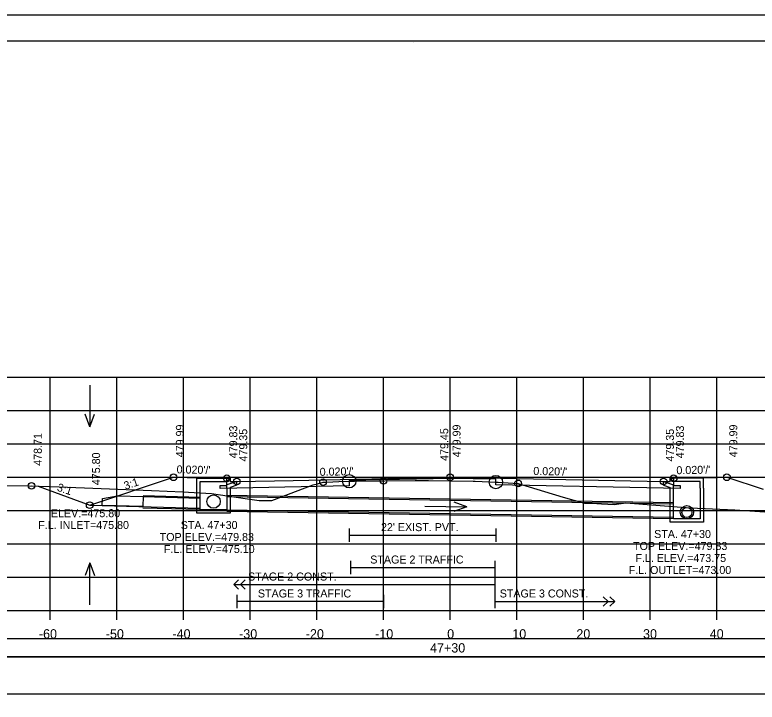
# Model space of a CAD drawing. Extents: x 1371057 to 1372761, y 380005 to 390517.
# Drawn here: x 1371495.6 to 1371606.9, y 382675.4 to 382778.5 of the extents above; entities that cross this region are included whole.
import ezdxf

# ---------------------------------------------------------------- set-up
doc = ezdxf.new("R2010")
doc.units = 0
for name, color, linetype in [('R_Alt Surface', 7, 'Continuous'), ('R_Axis', 7, 'Continuous'), ('R_Axis Annot', 7, 'Continuous'), ('R_Border', 7, 'Continuous'), ('R_Detour', 7, 'Continuous'), ('R_Dimension', 7, 'Continuous'), ('R_Exist Surface', 7, 'Continuous'), ('R_Fin Surface', 7, 'Continuous'), ('R_Grid', 7, 'Continuous'), ('R_No Plot', 7, 'Continuous'), ('R_Striping', 7, 'Continuous'), ('R_Water', 7, 'Continuous'), ('R_Water Annot', 7, 'Continuous'), ('R_Xsect Elev', 7, 'Continuous'), ('R_Xsect Slope', 7, 'Continuous')]:
    doc.layers.add(name, color=color, linetype=linetype)

msp = doc.modelspace()

# ---------------------------------------------------------------- linework, layer by layer
at = {"layer": 'R_Alt Surface'}
for points in [[(1371594.37, 382708.95), (1371594.37, 382707.87), (1371595.37, 382707.85), (1371595.37, 382707.42), (1371592.87, 382707.47), (1371567.72, 382707.97), (1371567.72, 382708.8), (1371560.87, 382708.94), (1371545.72, 382708.63), (1371545.72, 382707.8), (1371528.87, 382707.47), (1371526.37, 382707.42), (1371526.37, 382707.85), (1371527.37, 382707.87), (1371527.37, 382708.95)], [(1371594.37, 382708.95), (1371594.37, 382707.87), (1371595.37, 382707.85), (1371595.37, 382707.42), (1371592.87, 382707.47), (1371567.72, 382707.97), (1371567.72, 382708.8), (1371560.87, 382708.94), (1371545.72, 382708.63), (1371545.72, 382707.8), (1371528.87, 382707.47), (1371526.37, 382707.42), (1371526.37, 382707.85), (1371527.37, 382707.87), (1371527.37, 382708.95)], [(1371545.72, 382701.43), (1371545.72, 382699.43)], [(1371567.72, 382701.43), (1371567.72, 382699.43)], [(1371545.72, 382700.43), (1371567.72, 382700.43)]]:
    msp.add_lwpolyline(points, dxfattribs=at)
at = {"layer": 'R_Axis'}
for p, q in [((1371410.87, 382689.12), (1371710.87, 382689.12)), ((1371500.87, 382687.72), (1371500.87, 382689.12)), ((1371510.87, 382687.72), (1371510.87, 382689.12)), ((1371520.87, 382687.72), (1371520.87, 382689.12)), ((1371530.87, 382687.72), (1371530.87, 382689.12)), ((1371540.87, 382687.72), (1371540.87, 382689.12)), ((1371550.87, 382687.72), (1371550.87, 382689.12)), ((1371560.87, 382687.72), (1371560.87, 382689.12)), ((1371570.87, 382687.72), (1371570.87, 382689.12)), ((1371580.87, 382687.72), (1371580.87, 382689.12)), ((1371590.87, 382687.72), (1371590.87, 382689.12)), ((1371600.87, 382687.72), (1371600.87, 382689.12))]:
    msp.add_line(p, q, dxfattribs=at)
at = {"layer": 'R_Border'}
for p, q in [((1371402.87, 382774.58), (1371719.05, 382774.58)), ((1371555.39, 382774.32), (1371555.39, 382774.32)), ((1371555.39, 382774.32), (1371555.39, 382774.32))]:
    msp.add_line(p, q, dxfattribs=at)
at = {"layer": 'R_Detour'}
msp.add_lwpolyline([(1371407.72, 382682.16), (1371714.03, 382682.16), (1371714.03, 382684.87), (1371407.72, 382684.87)], close=True, dxfattribs=at)
at = {"layer": 'R_Dimension'}
msp.add_lwpolyline([(1371407.72, 382676.64), (1371714.03, 382676.64), (1371714.03, 382682.16), (1371407.72, 382682.16)], close=True, dxfattribs=at)
at = {"layer": 'R_Exist Surface'}
msp.add_lwpolyline([(1371492.96, 382707.86), (1371497.74, 382707.84), (1371502.2, 382707.69), (1371516.07, 382707.12), (1371520.75, 382706.94), (1371525.06, 382706.67), (1371530.11, 382705.9), (1371532.23, 382705.64), (1371533.39, 382705.63), (1371534.1, 382705.61), (1371539.13, 382707.52), (1371540.33, 382707.96), (1371540.98, 382708.13), (1371541.79, 382708.37), (1371542.34, 382708.39), (1371544.15, 382708.46), (1371545.72, 382708.52), (1371546.06, 382708.52), (1371546.51, 382708.53), (1371555.6, 382708.63), (1371556.12, 382708.63), (1371556.33, 382708.63), (1371556.87, 382708.62), (1371556.91, 382708.62), (1371556.91, 382708.62), (1371557.63, 382708.61), (1371564.29, 382708.51), (1371564.61, 382708.5), (1371567.72, 382708.38), (1371568.05, 382708.36), (1371571.04, 382708.19), (1371577.82, 382706.12), (1371581.01, 382705.24), (1371582.84, 382705.15), (1371583.56, 382705.1), (1371585.45, 382705.04), (1371587.2, 382705.26), (1371596.85, 382704.53), (1371603.55, 382704.22), (1371613.29, 382703.57)], dxfattribs=at)
at = {"layer": 'R_Fin Surface'}
msp.add_lwpolyline([(1371498.06, 382707.83), (1371499.08, 382707.79), (1371506.79, 382704.92), (1371506.79, 382704.92), (1371506.79, 382704.92), (1371519.37, 382709.11), (1371519.37, 382709.11), (1371519.37, 382709.11), (1371523.44, 382709.03), (1371524.37, 382709.01), (1371524.65, 382709), (1371527.37, 382708.95), (1371527.66, 382708.95), (1371527.87, 382708.95), (1371527.88, 382708.45), (1371528.87, 382708.47), (1371537.29, 382708.64), (1371560.87, 382709.11), (1371560.88, 382709.11), (1371570.93, 382708.91), (1371592.87, 382708.47), (1371593.71, 382708.45), (1371593.87, 382708.45), (1371593.87, 382708.68), (1371593.87, 382708.95), (1371593.95, 382708.95), (1371594.37, 382708.95), (1371597.37, 382709.01), (1371600.93, 382709.08), (1371602.37, 382709.11), (1371607.78, 382707.3)], dxfattribs=at)
at = {"layer": 'R_Grid'}
for p, q in [((1371410.87, 382724.12), (1371710.87, 382724.12)), ((1371500.87, 382689.12), (1371500.87, 382724.12)), ((1371510.87, 382689.12), (1371510.87, 382724.12)), ((1371520.87, 382689.12), (1371520.87, 382724.12)), ((1371530.87, 382689.12), (1371530.87, 382724.12)), ((1371540.87, 382689.12), (1371540.87, 382724.12)), ((1371550.87, 382689.12), (1371550.87, 382724.12)), ((1371560.87, 382689.12), (1371560.87, 382724.12)), ((1371570.87, 382689.12), (1371570.87, 382724.12)), ((1371580.87, 382689.12), (1371580.87, 382724.12)), ((1371590.87, 382689.12), (1371590.87, 382724.12)), ((1371600.87, 382689.12), (1371600.87, 382724.12)), ((1371410.87, 382719.12), (1371710.87, 382719.12)), ((1371410.87, 382714.12), (1371710.87, 382714.12)), ((1371410.87, 382709.12), (1371710.87, 382709.12)), ((1371410.87, 382704.12), (1371710.87, 382704.12)), ((1371410.87, 382699.12), (1371710.87, 382699.12)), ((1371410.87, 382694.12), (1371710.87, 382694.12)), ((1371410.87, 382689.12), (1371710.87, 382689.12))]:
    msp.add_line(p, q, dxfattribs=at)
at = {"layer": 'R_No Plot'}
for p, q in [((1371390.47, 382778.47), (1371723.8, 382778.47)), ((1371514.79, 382706.36), (1371523.37, 382706.13)), ((1371527.37, 382706.42), (1371594.37, 382705.32)), ((1371514.74, 382704.53), (1371523.37, 382704.3)), ((1371527.37, 382704.01), (1371594.37, 382702.9))]:
    msp.add_line(p, q, dxfattribs=at)
for points in [[(1371390.46, 382778.47), (1371723.8, 382778.47), (1371723.8, 382565.13), (1371390.46, 382565.13)], [(1371636.79, 382774.58), (1371656.41, 382774.58), (1371656.41, 382764.7), (1371672.52, 382764.7), (1371695.72, 382764.7), (1371695.84, 382736.54), (1371719.05, 382736.54), (1371719.05, 382569.12), (1371402.87, 382569.12), (1371402.87, 382774.58)]]:
    msp.add_lwpolyline(points, close=True, dxfattribs=at)
for centre, radius in [((1371519.37, 382709.11), 0.5), ((1371527.37, 382708.95), 0.5), ((1371528.87, 382708.47), 0.5), ((1371545.72, 382708.52), 1), ((1371550.87, 382708.58), 0.5), ((1371560.87, 382709.11), 0.5), ((1371567.72, 382708.38), 1), ((1371592.87, 382708.47), 0.5), ((1371594.37, 382708.95), 0.5), ((1371602.37, 382709.11), 0.5), ((1371498.06, 382707.83), 0.5), ((1371541.79, 382708.37), 0.5), ((1371571.04, 382708.19), 0.5), ((1371506.79, 382704.92), 0.5)]:
    msp.add_circle(centre, radius, dxfattribs=at)
at = {"layer": 'R_Striping'}
for p, q in [((1371545.9, 382696.57), (1371545.9, 382694.57)), ((1371545.9, 382695.57), (1371567.54, 382695.57)), ((1371567.54, 382696.57), (1371567.54, 382689.48)), ((1371528.41, 382693.02), (1371529.12, 382693.73)), ((1371529.41, 382693.02), (1371530.12, 382693.73)), ((1371528.41, 382693.02), (1371567.54, 382693.02)), ((1371529.12, 382692.31), (1371528.41, 382693.02)), ((1371530.12, 382692.31), (1371529.41, 382693.02)), ((1371528.87, 382691.48), (1371528.87, 382689.48)), ((1371550.87, 382691.48), (1371550.87, 382689.48)), ((1371584.54, 382690.48), (1371583.83, 382691.19)), ((1371585.54, 382690.48), (1371584.83, 382691.19)), ((1371550.87, 382690.48), (1371528.87, 382690.48)), ((1371567.54, 382690.48), (1371585.54, 382690.48)), ((1371567.57, 382690.48), (1371577.57, 382690.48)), ((1371583.83, 382689.77), (1371584.54, 382690.48)), ((1371584.83, 382689.77), (1371585.54, 382690.48))]:
    msp.add_line(p, q, dxfattribs=at)
at = {"layer": 'R_Water'}
for p, q in [((1371522.87, 382708.95), (1371527.62, 382708.95)), ((1371522.87, 382707.45), (1371522.87, 382708.95)), ((1371527.7, 382708.78), (1371527.62, 382708.95)), ((1371594.04, 382708.78), (1371594.12, 382708.95)), ((1371598.87, 382708.95), (1371594.12, 382708.95)), ((1371598.87, 382707.45), (1371598.87, 382708.95)), ((1371523.37, 382707.45), (1371523.37, 382708.45)), ((1371523.37, 382708.45), (1371527.37, 382708.45)), ((1371527.7, 382708.78), (1371527.37, 382708.45)), ((1371528.87, 382708.47), (1371527.37, 382707.95)), ((1371527.37, 382707.45), (1371527.37, 382707.95)), ((1371528.87, 382707.94), (1371527.87, 382707.59)), ((1371592.87, 382708.47), (1371594.37, 382707.95)), ((1371592.87, 382707.94), (1371593.87, 382707.59)), ((1371594.04, 382708.78), (1371594.37, 382708.45)), ((1371598.37, 382708.45), (1371594.37, 382708.45)), ((1371594.37, 382707.45), (1371594.37, 382707.95)), ((1371598.37, 382707.45), (1371598.37, 382708.45)), ((1371527.87, 382707.45), (1371527.87, 382707.59)), ((1371593.87, 382707.45), (1371593.87, 382707.59)), ((1371514.79, 382706.2), (1371523.37, 382705.97)), ((1371527.37, 382706.22), (1371594.37, 382705.11)), ((1371506.79, 382704.92), (1371523.37, 382704.47)), ((1371527.37, 382704.22), (1371594.37, 382703.11))]:
    msp.add_line(p, q, dxfattribs=at)
for points in [[(1371528.87, 382707.94), (1371528.87, 382708.47)], [(1371592.87, 382707.94), (1371592.87, 382708.47)], [(1371527.87, 382707.45), (1371527.87, 382703.72), (1371525.37, 382703.72), (1371522.87, 382703.72), (1371522.87, 382707.45)], [(1371527.37, 382707.45), (1371527.37, 382704.22), (1371525.37, 382704.22), (1371523.37, 382704.22), (1371523.37, 382707.45)], [(1371598.87, 382707.45), (1371598.87, 382702.37), (1371596.37, 382702.37), (1371593.87, 382702.37), (1371593.87, 382707.45)], [(1371598.37, 382707.45), (1371598.37, 382702.87), (1371596.37, 382702.87), (1371594.37, 382702.87), (1371594.37, 382707.45)]]:
    msp.add_lwpolyline(points, dxfattribs=at)
msp.add_lwpolyline([(1371514.79, 382706.2), (1371514.75, 382704.7), (1371508.67, 382704.86), (1371508.69, 382705.9), (1371510.96, 382706.3)], close=True, dxfattribs=at)
for centre, radius in [((1371525.37, 382705.47), 1), ((1371596.37, 382703.87), 1), ((1371596.37, 382703.83), 0.75)]:
    msp.add_circle(centre, radius, dxfattribs=at)
at = {"layer": 'R_Water Annot'}
for p, q in [((1371506.79, 382722.94), (1371506.79, 382716.66)), ((1371506.79, 382716.66), (1371506.09, 382718.58)), ((1371506.79, 382716.66), (1371507.49, 382718.58)), ((1371557.07, 382704.75), (1371563.35, 382704.65)), ((1371563.35, 382704.65), (1371561.41, 382703.98)), ((1371563.35, 382704.65), (1371561.44, 382705.38)), ((1371506.79, 382696.28), (1371506.09, 382694.35)), ((1371506.79, 382689.99), (1371506.79, 382696.28)), ((1371506.79, 382696.28), (1371507.49, 382694.35))]:
    msp.add_line(p, q, dxfattribs=at)
at = {"layer": 'R_Xsect Elev'}
msp.add_line((1371560.87, 382708.56), (1371560.87, 382718.56), dxfattribs=at)

# ---------------------------------------------------------------- texts
at = {"layer": 'R_Axis Annot'}
for s, p in [('-60', (1371499.18, 382684.92)), ('-50', (1371509.21, 382684.92)), ('-40', (1371519.21, 382684.92)), ('-30', (1371529.21, 382684.92)), ('-20', (1371539.21, 382684.92)), ('-10', (1371549.61, 382684.92)), ('0', (1371560.41, 382684.92)), ('10', (1371570.18, 382684.92)), ('20', (1371579.79, 382684.92)), ('30', (1371589.79, 382684.92)), ('40', (1371599.79, 382684.92)), ('47+30', (1371557.85, 382682.82))]:
    msp.add_text(s, height=1.4, dxfattribs=at).set_placement(p)
at = {"layer": 'R_Striping'}
for s, p in [('STAGE 2 TRAFFIC', (1371548.87, 382696.17)), ('STAGE 2 CONST.', (1371530.54, 382693.62)), ('STAGE 3 TRAFFIC', (1371532.02, 382691.08)), ('STAGE 3 CONST.', (1371568.29, 382691.08))]:
    msp.add_text(s, height=1.2, dxfattribs=at).set_placement(p)
at = {"layer": 'R_Water'}
msp.add_text("22' EXIST. PVT.", height=1.2, dxfattribs=at).set_placement((1371550.48, 382701.03))
at = {"layer": 'R_Water Annot'}
for s, p in [('F.L. INLET=475.80', (1371499.08, 382701.35)), ('STA. 47+30', (1371520.45, 382701.35)), ('STA. 47+30', (1371591.45, 382700)), ('TOP ELEV.=479.83', (1371517.29, 382699.55)), ('F.L. ELEV.=475.10', (1371517.93, 382697.75)), ('TOP ELEV.=479.83', (1371588.29, 382698.2)), ('F.L. ELEV.=473.75', (1371588.64, 382696.4)), ('F.L. OUTLET=473.00', (1371587.63, 382694.6))]:
    msp.add_text(s, height=1.2, dxfattribs=at).set_placement(p)
at = {"layer": 'R_Xsect Elev'}
for s, p in [('479.99', (1371520.92, 382712.11)), ('479.83', (1371528.92, 382711.95)), ('479.99', (1371562.42, 382712.11)), ('479.83', (1371595.92, 382711.95)), ('479.99', (1371603.92, 382712.11)), ('478.71', (1371499.61, 382710.83)), ('479.35', (1371530.42, 382711.47)), ('479.45', (1371560.57, 382711.56)), ('479.35', (1371594.42, 382711.47)), ('475.80', (1371508.35, 382707.92))]:
    msp.add_text(s, height=1.2, rotation=90, dxfattribs=at).set_placement(p)
msp.add_text('ELEV.=475.80', height=1.2, dxfattribs=at).set_placement((1371500.97, 382703.12))
at = {"layer": 'R_Xsect Slope'}
for s, rotation, p in [("0.020'/'", 358.8543, (1371519.82, 382709.7)), ("0.020'/'", 1.1457, (1371541.3, 382709.32)), ("0.020'/'", 358.8542, (1371573.32, 382709.46)), ("0.020'/'", 1.1458, (1371594.8, 382709.56)), ('3:1', 18.4333, (1371512.14, 382707.22)), ('3:1', 341.5651, (1371501.8, 382707.11))]:
    msp.add_text(s, height=1.2, rotation=rotation, dxfattribs=at).set_placement(p)

doc.saveas('drawing.dxf')
